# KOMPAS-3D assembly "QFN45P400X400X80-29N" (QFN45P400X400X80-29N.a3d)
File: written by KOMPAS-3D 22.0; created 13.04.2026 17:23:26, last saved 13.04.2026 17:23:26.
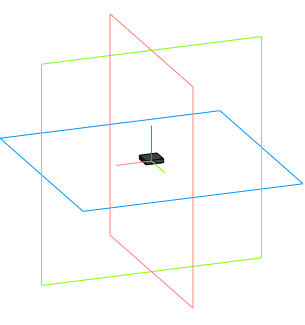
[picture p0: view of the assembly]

Document properties: Автор: Andrey; Полное имя файла: C:\Users\User1\Documents\QFN45P400X400X80-29N.a3d

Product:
- Component [detail]: ES8388  | qty 1  | source file: ES8388.m3d
- Part/product: QFN45P400X400X80-29N
    Комментарий: QFN45P400X400X80-29N

Expressions: QFN45P400X400X80-29N
Referenced files in C:\Users\User1\Documents\: ES8388.m3d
